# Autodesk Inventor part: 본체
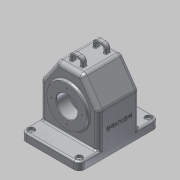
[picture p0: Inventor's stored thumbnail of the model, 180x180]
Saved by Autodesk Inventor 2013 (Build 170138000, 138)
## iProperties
Created: 2016-12
Part Number: 본체
Material: 알루미늄 6061
Document SubType Name: Modeling
Designer: Administrator
Density: 2.71 g/cm^3
Mass: 1067.99 g
Surface Area: 1140.38 cm^2
Volume: 394.094 cm^3
Author: Administrator
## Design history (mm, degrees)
sketch "스케치1"
  geometry: L1 (-55, -38.5)-(55, -38.5); L2 (55, -38.5)-(55, 38.5); L3 (55, 38.5)-(-55, 38.5); L4 (-55, 38.5)-(-55, -38.5); L5 (-55, -38.5)-(55, 38.5); L6 (55, -38.5)-(-55, 38.5); 1 further point
  constraints: 12 end point, 2 midpoint, 2 parallel, 1 horizontal, 1 perpendicular
  dimensions: "d0" = 110 distance of L1.start L1.end; "d2" = 77 distance of L3.end L1.start
extrude "돌출1" new body sketch "스케치1" distance "d3" = 125; taper "d4" = 0 deg
sketch "스케치2"
  geometry: L1 (0, 0)-(110, 0) reference; L2 (110, 0)-(110, 125) reference; L3 (0, 125)-(110, 125) reference; L4 (0, 0)-(0, 125) reference; L5 (0, 80)-(31.509, 125); L6 (78.491, 125)-(110, 80); 1 further point
  constraints: 4 end point, 4 point on line
  dimensions: "d5" = 35 deg angle of L5 L4; "d6" = 35 deg angle of L2 L6; "d7" = 80 distance from line of L1 L5.start; "d8" = 80 distance from line of L1 L6.end
extrude "돌출2" cut sketch "스케치2" stored distance "d9" = 125; taper "d10" = 0 deg
feature "쉘1" dims "d11" = 5
sketch "스케치3"
  geometry: L1 (0, 0)-(110, 0) reference; C1 r 37.5 at (55, 65); 2 further points
  constraints: 1 centre point, 1 midpoint, 1 vertical alignment
  dimensions: "d12" = 75 diameter of C1; "d14" = 65 distance from line of C1.centre L1
extrude "돌출3" join sketch "스케치3" distance "d15" = 5; taper "d16" = 0 deg
sketch "스케치4"
  geometry: L1 (110, 0)-(0, 0) reference; C1 r 31 at (55, -65); 2 further points
  constraints: 1 centre point, 1 midpoint, 1 vertical alignment
  dimensions: "d17" = 62 diameter of C1; "d19" = 65 distance from line of C1.centre L1
extrude "돌출4" join sketch "스케치4" distance "d20" = 10; taper "d21" = 0 deg
fillet "모깎기1" dims "d22" = 8
fillet "모깎기2" dims "d23" = 3
sketch "스케치5"
  geometry: L1 (-33.5, 117)-(-33.5, 77.478) reference; L2 (-33.5, 77.478)-(-33.5, 0) reference; L3 (-33.5, 106)-(-19.5, 92); L4 (-19.5, 92)-(-19.5, 85); L5 (-19.5, 85)-(-33.5, 85); L6 (33.5, 0)-(33.5, 77.478) reference; L7 (-33.5, 65)-(33.5, 65); L8 (-43.5, 102.5)-(-43.5, 27.5) reference; L9 (-33.5, 85)-(-33.5, 106); 1 further point
  constraints: 10 end point, 4 point on line, 2 parallel, 2 perpendicular
  dimensions: "d24" = 65 distance from line of point (0, 0) L7; "d25" = 24 distance between parallel lines of L4 L8; "d26" = 40 diameter of L5 L7; "d27" = 45 deg angle of L4 L3; "d28" = 54 diameter of L3.end L7
revolve "회전1" sketch "스케치5" stored, may be unused: angle "d29" = 90 deg
sketch "스케치6"
  geometry: C1 r 37.5 at (0, 0) reference; C2 r 20 at (0, 0); 1 further point
  constraints: 1 centre point, 1 coincident
  dimensions: "d30" = 40 diameter of C2
extrude "돌출5" cut sketch "스케치6" stored distance "d32" = 10; taper "d33" = 0 deg
fillet "모깎기3" dims "d34" = 3
sketch "스케치7"
  geometry: L1 (-55, -30.5)-(-55, 30.5) reference; L2 (47, -38.5)-(-47, -38.5) reference; L3 (55, 30.5)-(55, -30.5) reference; L4 (-47, 38.5)-(47, 38.5) reference; L5 (-55, -75)-(55, -75); L6 (55, -75)-(55, 75); L7 (55, 75)-(-55, 75); L8 (-55, 75)-(-55, -75); L9 (-55, -75)-(55, 75); L10 (55, -75)-(-55, 75); A1 r 8 centre (-47, 30.5) between (-47, 38.5) and (-55, 30.5) reference; A2 r 8 centre (-47, -30.5) between (-55, -30.5) and (-47, -38.5) reference; A3 r 8 centre (47, -30.5) between (47, -38.5) and (55, -30.5) reference; A4 r 8 centre (47, 30.5) between (55, 30.5) and (47, 38.5) reference; 1 further point
  constraints: 12 end point, 2 midpoint, 2 parallel, 1 horizontal, 1 perpendicular
  dimensions: "d35" = 110 distance of L6.end L7.end; "d37" = 150 distance of L7.end L5.start
extrude "돌출6" join sketch "스케치7" distance "d38" = 15; taper "d39" = 0 deg
fillet "모깎기4" dims "d40" = 10
sketch "스케치8"
  geometry: A1 r 10 centre (45, 65) between (55, 65) and (45, 75) reference; A2 r 10 centre (-45, 65) between (-45, 75) and (-55, 65) reference; A3 r 10 centre (-45, -65) between (-55, -65) and (-45, -75) reference; A4 r 10 centre (45, -65) between (45, -75) and (55, -65) reference; 1 further point
hole "구멍1" sketch "스케치8" at (-45, 65), (-45, -65), (45, -65), (45, 65) diameter "d41" = 5; stored, may be unused: countersink angle "d45" = 90 deg, drill point angle "d47" = 0 deg; dims "d42" = 6, "d43" = 12, "d44" = 5, "d46" = 8
fillet "모깎기5" dims "d48" = 3
sketch "스케치9"
  geometry: L1 (-12.5, -26)-(12.5, -26); L2 (12.5, -26)-(12.5, -18); L3 (12.5, -18)-(-12.5, -18); L4 (-12.5, -18)-(-12.5, -26); L5 (-12.5, -26)-(12.5, -18); L6 (12.5, -26)-(-12.5, -18); L7 (-12.5, 18)-(12.5, 18); L8 (12.5, 18)-(12.5, 26); L9 (12.5, 26)-(-12.5, 26); L10 (-12.5, 26)-(-12.5, 18); L11 (-12.5, 18)-(12.5, 26); L12 (12.5, 18)-(-12.5, 26); 5 further points
  constraints: 24 end point, 6 midpoint, 4 parallel, 2 horizontal, 2 perpendicular, 2 vertical alignment
  dimensions: "d49" = 36 distance between parallel lines of L3 L7; "d51" = 18 distance from line of point (0, 0) L7; "d52" = 52 distance between parallel lines of L1 L9; "d53" = 25 distance between parallel lines of L2 L4; "d54" = 25 distance between parallel lines of L8 L10; "d55" = 26 distance from line of point (0, 0) L9
extrude "돌출7" join sketch "스케치9" distance "d56" = 15; taper "d57" = 0 deg
sketch "스케치10"
  geometry: L1 (25, 0)-(0, 0) reference; L2 (0, 15)-(25, 15) reference; L3 (5, 10)-(20, 10); L4 (20, 10)-(20, 0); L5 (20, 0)-(5, 0); L6 (5, 0)-(5, 10); C1 r 20 at (12.5, -60) reference; 1 further point
  constraints: 8 end point, 2 parallel, 1 horizontal, 1 perpendicular, 1 point on line
  dimensions: "d58" = 15 distance between parallel lines of L4 L6; "d60" = 7.5 distance from line of C1.centre L6; "d61" = 5 distance between parallel lines of L3 L2
extrude "돌출8" cut sketch "스케치10" stored distance "d62" = 15; taper "d63" = 0 deg
sketch "스케치11"
  geometry: C1 r 20 at (0, 0) reference; 2 further points
  constraints: 1 vertical alignment
  dimensions: "d70" = 29 distance of C1.centre point (0, 29)
hole "구멍2" sketch "스케치11" at (0, 29) diameter "d71" = 2.459; stored, may be unused: countersink angle "d75" = 90 deg, drill point angle "d77" = 118 deg; dims "d72" = 6, "d73" = 12, "d74" = 5, "d76" = 8
sketch "스케치12"
  geometry: C1 r 20 at (0, 0) reference; 2 further points
  constraints: 1 vertical alignment
  dimensions: "d81" = 26 distance of C1.centre point (0, 26)
hole "구멍3" sketch "스케치12" at (0, 26) diameter "d82" = 2.459; stored, may be unused: countersink angle "d86" = 90 deg, drill point angle "d88" = 118 deg; dims "d83" = 6, "d84" = 12, "d85" = 5, "d87" = 8
sketch "스케치13"
  geometry: L1 (77.478, 95.5)-(77.478, -34.5) reference; L2 (45.691, 5.613)-(45.691, 55.387); L3 (45.691, 55.387)-(19.265, 55.387); L4 (19.265, 55.387)-(19.265, 5.613); L5 (19.265, 5.613)-(45.691, 5.613); L6 (45.691, 30.5)-(19.265, 30.5); L7 (32.478, 5.613)-(32.478, 55.387); L8 (0, -8)-(59.478, -8) reference; 2 further points
  constraints: 5 midpoint, 4 end point, 2 other
  dimensions: "d92" = 45 distance between parallel lines of L1 L7; "d93" = 38.5 distance between parallel lines of L6 L8
extrude "돌출9" join sketch "스케치13" distance "d94" = 0.5; taper "d95" = 0 deg
fillet "모깎기12" dims "d96" = 8, "d97" = 3
fillet "모깎기13" dims "d98" = 1
chamfer "모따기1" distance "d99" = 1; stored, may be unused: second distance "d100" = 2, angle "d101" = 45 deg
node "솔리드1"
pattern_circular "원형 패턴1" dims angle "d79" = 360 deg
pattern_circular "원형 패턴2" dims angle "d90" = 360 deg
